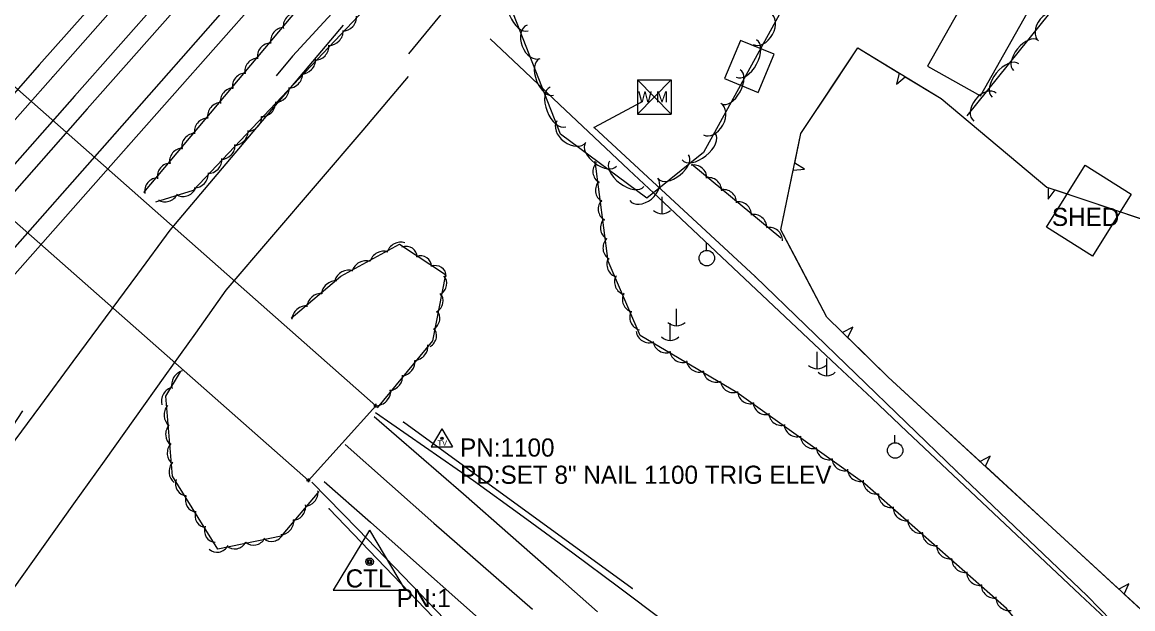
# Model space of a CAD drawing. Extents: x 1441650 to 1491889, y 345904 to 358319.
# Drawn here: x 1442949.9 to 1443255.9, y 356710.4 to 356872.1 of the extents above; entities that cross this region are included whole.
import ezdxf

# ---------------------------------------------------------------- set-up
doc = ezdxf.new("R2010")
doc.units = 0
for name, color, linetype in [('S_BRIDGE', 7, 'Continuous'), ('S_BUILDING', 7, 'Continuous'), ('S_BUILDING_ANNOT', 7, 'Continuous'), ('S_EDGE_PAVEMENT', 7, 'Continuous'), ('S_GRAVEL_ROAD', 7, 'Continuous'), ('S_GUARDRAIL', 7, 'Continuous'), ('S_MSC_PT_SYM', 7, 'Continuous'), ('S_PAVEMENT_CROWN', 7, 'Continuous'), ('S_PRIMARY_CTL', 7, 'Continuous'), ('S_PRIMARY_CTL_ANNOT', 7, 'Continuous'), ('S_RAILROAD', 7, 'Continuous'), ('S_RDW_PT_SYM', 7, 'Continuous'), ('S_SECONDARY_CTL', 7, 'Continuous'), ('S_SECONDARY_CTL_ANNOT', 7, 'Continuous'), ('S_SHOULDER', 7, 'Continuous'), ('S_STR_PT_SYM', 7, 'Continuous'), ('S_STREAM', 7, 'Continuous'), ('S_TREE', 7, 'Continuous'), ('S_UTILITY_POLE', 7, 'Continuous'), ('S_UTL_PT_SYM', 7, 'Continuous'), ('S_WATER_UTILITIES', 7, 'Continuous')]:
    doc.layers.add(name, color=color, linetype=linetype)

msp = doc.modelspace()

# ---------------------------------------------------------------- linework, layer by layer
at = {"layer": 'S_BRIDGE'}
for p, q in [((1443047.33, 356766.4), (1442874.85, 356918.79)), ((1442856.36, 356897.86), (1443028.8, 356745.81)), ((1443028.8, 356745.81), (1443047.33, 356766.4))]:
    msp.add_line(p, q, dxfattribs=at)
at = {"layer": 'S_BUILDING'}
for points in [[(1443227.57, 356909.94), (1443199.41, 356859.94), (1443213.93, 356851.76), (1443231.22, 356882.45), (1443236.84, 356879.29), (1443243.13, 356890.47), (1443237.53, 356893.62), (1443242.11, 356901.75)], [(1443152.76, 356852.67), (1443157.13, 356863.23), (1443147.85, 356867.08), (1443143.48, 356856.52)], [(1443255.53, 356824.71), (1443244.86, 356807.61), (1443232.12, 356815.56), (1443242.79, 356832.66)]]:
    msp.add_lwpolyline(points, close=True, dxfattribs=at)
at = {"layer": 'S_EDGE_PAVEMENT'}
for points in [[(1443046.95, 356763.46), (1443059.25, 356752.76), (1443071.55, 356742.07), (1443084.44, 356730.75), (1443097.33, 356719.43), (1443108.42, 356709.61)], [(1443033.16, 356745.54), (1443045.88, 356734.26), (1443058.61, 356722.97), (1443070.75, 356712.18), (1443082.9, 356701.4)]]:
    msp.add_lwpolyline(points, dxfattribs=at)
at = {"layer": 'S_GRAVEL_ROAD'}
for points in [[(1443151.63, 356970.73), (1443074.25, 356885.2), (1443056.37, 356863.33)], [(1443038.34, 356871.29), (1443026.4, 356857.15), (1443014.47, 356843.02), (1443002.53, 356828.88), (1442990.6, 356814.74), (1442981.69, 356802.67), (1442972.78, 356790.61), (1442963.86, 356778.54), (1442954.95, 356766.48), (1442946.04, 356754.42), (1442937.13, 356742.35), (1442928.22, 356730.29), (1442919.3, 356718.22)], [(1443056.32, 356857.08), (1443043.75, 356842.36), (1443031.19, 356827.64), (1443018.62, 356812.92), (1443006.05, 356798.21), (1442997.66, 356786.43), (1442989.27, 356774.66), (1442980.88, 356762.89), (1442972.5, 356751.12), (1442964.11, 356739.35), (1442955.72, 356727.58), (1442947.33, 356715.81), (1442938.94, 356704.04)]]:
    msp.add_lwpolyline(points, dxfattribs=at)
at = {"layer": 'S_GUARDRAIL'}
for p, q in [((1443118.01, 356716.01), (1443054.97, 356761.85)), ((1443034.47, 356738), (1443088.44, 356681.87))]:
    msp.add_line(p, q, dxfattribs=at)
at = {"layer": 'S_MSC_PT_SYM'}
for points in [[(1442954.65, 356860.32), (1442954.65, 356860.37), (1442954.65, 356860.32), (1442954.6, 356860.32), (1442954.65, 356860.32), (1442954.65, 356860.27), (1442954.65, 356860.32), (1442954.7, 356860.32)], [(1442958.34, 356857.04), (1442958.34, 356857.09), (1442958.34, 356857.04), (1442958.29, 356857.04), (1442958.34, 356857.04), (1442958.34, 356856.99), (1442958.34, 356857.04), (1442958.39, 356857.04)], [(1442964.33, 356851.66), (1442964.33, 356851.71), (1442964.33, 356851.66), (1442964.28, 356851.66), (1442964.33, 356851.66), (1442964.33, 356851.61), (1442964.33, 356851.66), (1442964.38, 356851.66)], [(1442967.86, 356848.17), (1442967.86, 356848.22), (1442967.86, 356848.17), (1442967.81, 356848.17), (1442967.86, 356848.17), (1442967.86, 356848.12), (1442967.86, 356848.17), (1442967.91, 356848.17)], [(1442975.36, 356841.21), (1442975.36, 356841.26), (1442975.36, 356841.21), (1442975.31, 356841.21), (1442975.36, 356841.21), (1442975.36, 356841.16), (1442975.36, 356841.21), (1442975.41, 356841.21)], [(1442979.24, 356838.14), (1442979.24, 356838.19), (1442979.24, 356838.14), (1442979.19, 356838.14), (1442979.24, 356838.14), (1442979.24, 356838.09), (1442979.24, 356838.14), (1442979.29, 356838.14)]]:
    msp.add_lwpolyline(points, dxfattribs=at)
at = {"layer": 'S_PAVEMENT_CROWN'}
msp.add_lwpolyline([(1443038.95, 356755.67), (1443051.16, 356744.86), (1443063.38, 356734.04), (1443076.96, 356722.17), (1443090.55, 356710.29)], dxfattribs=at)
at = {"layer": 'S_PRIMARY_CTL'}
for p, q in [((1443045.64, 356732.08), (1443035.6, 356715.57)), ((1443045.64, 356732.08), (1443055.46, 356715.57)), ((1443035.6, 356715.57), (1443055.46, 356715.57))]:
    msp.add_line(p, q, dxfattribs=at)
for radius in [1.04, 0.609, 0.344]:
    msp.add_circle((1443045.64, 356723.38), radius, dxfattribs=at)
at = {"layer": 'S_RAILROAD'}
for p, q in [((1442986.62, 356896.5), (1442954.65, 356860.32)), ((1442990.28, 356893.3), (1442958.34, 356857.04)), ((1442995.68, 356887.17), (1442964.33, 356851.66)), ((1442999.05, 356883.51), (1442967.86, 356848.17)), ((1443011.76, 356882.6), (1442975.36, 356841.21)), ((1443016.65, 356880.49), (1442979.24, 356838.14)), ((1442954.65, 356860.32), (1442867.45, 356761.69)), ((1442958.34, 356857.04), (1442871.11, 356758.37)), ((1442964.33, 356851.66), (1442876.67, 356752.43)), ((1442967.86, 356848.17), (1442880.75, 356749.56)), ((1442975.36, 356841.21), (1442888.71, 356743.18)), ((1442979.24, 356838.14), (1442889.38, 356736.56))]:
    msp.add_line(p, q, dxfattribs=at)
at = {"layer": 'S_RDW_PT_SYM'}
for points in [[(1443054.97, 356761.85), (1443054.97, 356761.9), (1443054.97, 356761.85), (1443054.92, 356761.85), (1443054.97, 356761.85), (1443054.97, 356761.8), (1443054.97, 356761.85), (1443055.02, 356761.85)], [(1443034.47, 356738), (1443034.47, 356738.05), (1443034.47, 356738), (1443034.42, 356738), (1443034.47, 356738), (1443034.47, 356737.95), (1443034.47, 356738), (1443034.52, 356738)], [(1443118.01, 356716.01), (1443118.01, 356716.06), (1443118.01, 356716.01), (1443117.96, 356716.01), (1443118.01, 356716.01), (1443118.01, 356715.96), (1443118.01, 356716.01), (1443118.06, 356716.01)]]:
    msp.add_lwpolyline(points, dxfattribs=at)
at = {"layer": 'S_SECONDARY_CTL'}
for p, q in [((1443065.58, 356759.98), (1443062.57, 356755.03)), ((1443065.58, 356759.98), (1443068.53, 356755.03)), ((1443062.57, 356755.03), (1443068.53, 356755.03))]:
    msp.add_line(p, q, dxfattribs=at)
for radius in [0.311, 0.183, 0.103]:
    msp.add_circle((1443065.58, 356757.37), radius, dxfattribs=at)
at = {"layer": 'S_SHOULDER'}
for points in [[(1443047.24, 356764.51), (1443060.77, 356755.17), (1443074.29, 356745.83), (1443087.97, 356735.86), (1443101.65, 356725.88), (1443114.21, 356716.46), (1443126.77, 356707.03)], [(1443029.77, 356745.36), (1443042.4, 356732.34), (1443055.03, 356719.33), (1443066.3, 356707.56)]]:
    msp.add_lwpolyline(points, dxfattribs=at)
at = {"layer": 'S_STR_PT_SYM'}
for points in [[(1443047.33, 356766.4), (1443047.33, 356766.9), (1443047.33, 356766.4), (1443046.83, 356766.4), (1443047.33, 356766.4), (1443047.33, 356765.9), (1443047.33, 356766.4), (1443047.83, 356766.4)], [(1443028.8, 356745.81), (1443028.8, 356746.31), (1443028.8, 356745.81), (1443028.3, 356745.81), (1443028.8, 356745.81), (1443028.8, 356745.31), (1443028.8, 356745.81), (1443029.3, 356745.81)]]:
    msp.add_lwpolyline(points, dxfattribs=at)
at = {"layer": 'S_STREAM'}
for points in [[(1443131.3, 356979.88), (1443092.22, 356939.62), (1443051.39, 356892.12), (1443024.43, 356862.76), (1443019.87, 356857.32)], [(1442840.69, 356611.56), (1442873.28, 356652.88), (1442908.54, 356701.31), (1442950.1, 356764.98)]]:
    msp.add_lwpolyline(points, dxfattribs=at)
at = {"layer": 'S_TREE'}
for p, q in [((1443191.57, 356858.08), (1443190.81, 356855.03)), ((1443190.81, 356855.03), (1443193.25, 356857.06)), ((1443165.52, 356831.61), (1443162.79, 356833.21)), ((1443162.39, 356831.29), (1443165.52, 356831.61)), ((1443232.66, 356826.49), (1443232.6, 356823.35)), ((1443232.6, 356823.35), (1443234.52, 356825.87)), ((1443178.8, 356788.02), (1443175.97, 356786.58)), ((1443177.38, 356785.21), (1443178.8, 356788.02)), ((1443216.64, 356752.53), (1443213.86, 356751.02)), ((1443215.31, 356749.69), (1443216.64, 356752.53)), ((1443254.89, 356717.35), (1443252.11, 356715.84)), ((1443253.55, 356714.5), (1443254.89, 356717.35))]:
    msp.add_line(p, q, dxfattribs=at)
for points in [[(1442983.48, 356825.12), (1443029.8, 356880.45), (1443068.95, 356927.1), (1443105.36, 356970.5), (1443136.89, 357005.23)], [(1443123.74, 356966.97), (1443045.8, 356877.25), (1442997.01, 356825.66), (1442986.67, 356822.44)], [(1443171.84, 356898.42), (1443137.65, 356836.14), (1443122, 356823.6), (1443098.21, 356841.22), (1443083.64, 356878.65), (1443109.92, 356917.08), (1443145.8, 356959.84)], [(1443210.26, 356846.31), (1443233.07, 356874.55), (1443252.62, 356884.24)], [(1443078.86, 356867.47), (1443088.43, 356858.46), (1443097.99, 356849.44), (1443107.56, 356840.43), (1443117.12, 356831.42), (1443126.69, 356822.41), (1443136.26, 356813.4), (1443145.82, 356804.39), (1443155.39, 356795.38), (1443164.96, 356786.37), (1443174.52, 356777.36), (1443184.09, 356768.34), (1443193.65, 356759.33), (1443203.22, 356750.32), (1443212.79, 356741.31), (1443222.35, 356732.3), (1443231.92, 356723.29), (1443241.48, 356714.28), (1443251.05, 356705.27)], [(1443078.86, 356867.47), (1443088.43, 356858.46), (1443097.99, 356849.44), (1443107.56, 356840.43), (1443117.12, 356831.42), (1443126.69, 356822.41), (1443136.26, 356813.4), (1443145.82, 356804.39), (1443155.39, 356795.38), (1443164.96, 356786.37), (1443174.52, 356777.36), (1443184.09, 356768.34), (1443193.65, 356759.33), (1443203.22, 356750.32), (1443212.79, 356741.31), (1443222.35, 356732.3), (1443231.92, 356723.29), (1443241.48, 356714.28), (1443251.05, 356705.27)], [(1443505.41, 356683.7), (1443488.39, 356651.81), (1443461.07, 356631.7), (1443424.93, 356601.52), (1443377, 356634.15), (1443309.47, 356701.91), (1443277.71, 356692.29), (1443188.57, 356774.28), (1443171.66, 356790.8), (1443158.99, 356814.85), (1443164.48, 356841.38), (1443180.21, 356864.99), (1443203.13, 356851.04), (1443232.22, 356826.64), (1443267.71, 356814.76), (1443299.03, 356809.84), (1443326.75, 356811.76), (1443339.28, 356826.69)], [(1443173.72, 356855.25), (1443180.21, 356864.99), (1443191.57, 356858.08)], [(1443193.25, 356857.06), (1443203.13, 356851.04), (1443213.42, 356842.42)], [(1443162.79, 356833.21), (1443164.48, 356841.38), (1443173.72, 356855.25)], [(1443213.42, 356842.42), (1443232.22, 356826.64), (1443232.66, 356826.49)], [(1443313.71, 356643.52), (1443306.08, 356628.88), (1443297.66, 356624.12), (1443265.96, 356656.62), (1443221.16, 356710.52), (1443182.13, 356744.91), (1443146.86, 356770.04), (1443120.24, 356785.78), (1443111.42, 356806.27), (1443107.79, 356833.75)], [(1443134.48, 356832.94), (1443158.95, 356812.69)], [(1443162.82, 356807.58), (1443158.99, 356814.85), (1443162.39, 356831.29)], [(1443234.52, 356825.87), (1443258.23, 356817.93)], [(1443024.03, 356790.49), (1443037.75, 356802.12), (1443053.93, 356810.94), (1443066.58, 356802.55), (1443062.95, 356784.27), (1443047.75, 356765.83)], [(1443175.97, 356786.58), (1443171.66, 356790.8), (1443162.82, 356807.58)], [(1443195.46, 356767.94), (1443188.57, 356774.28), (1443177.38, 356785.21)], [(1443031.65, 356742.72), (1443021.25, 356730.46), (1443003.84, 356726.88), (1442991.3, 356747.02), (1442989.51, 356769.04), (1442993.51, 356775.69)], [(1443213.86, 356751.02), (1443195.46, 356767.94)], [(1443233.71, 356732.76), (1443215.31, 356749.69)], [(1443252.11, 356715.84), (1443233.71, 356732.76)], [(1443271.95, 356697.58), (1443253.55, 356714.5)]]:
    msp.add_lwpolyline(points, dxfattribs=at)
for centre in [(1443134.96, 356829.09), (1443139.02, 356825.63), (1443143.14, 356822.32), (1443147.25, 356818.97), (1443151.44, 356815.49), (1443155.77, 356811.87)]:
    msp.add_arc(centre, 3.64, 359.5936, 101.1906, dxfattribs=at)
for centre, major_axis, ratio, start_param, end_param in [((1443087.25, 356875.21), (2.13, -5.47), 0.550077, 3.141593, 6.283185), ((1443233.08, 356870.78), (-3.11, -3.86), 0.684333, 3.141593, 6.283185), ((1443025.43, 356871.09), (-2.45, -2.7), 0.970025, 3.866419, 5.63962), ((1443038.65, 356873.11), (2.49, 2.66), 0.892116, 3.819515, 5.592715), ((1443153.69, 356870.3), (2.38, 4.34), 0.685297, 3.141593, 6.283185), ((1443021.95, 356867.05), (-2.45, -2.7), 0.970025, 3.866419, 5.63962), ((1443034.91, 356869.15), (2.49, 2.66), 0.892116, 3.819515, 5.592715), ((1443090.86, 356866.68), (1.8, -4.62), 0.685307, 3.141593, 6.283185), ((1443018.3, 356862.74), (-2.45, -2.7), 0.970025, 3.866419, 5.63962), ((1443031.01, 356865.07), (2.49, 2.66), 0.892116, 3.819515, 5.592715), ((1443149.46, 356862.06), (2.82, 5.14), 0.550069, 3.141593, 6.283185), ((1443226.41, 356862.93), (-3.36, -4.16), 0.539928, 3.141593, 6.283185), ((1443014.81, 356858.57), (-2.45, -2.7), 0.970025, 3.866419, 5.63962), ((1443027.3, 356861.24), (2.49, 2.66), 0.892116, 3.819515, 5.592715), ((1443094.35, 356856.98), (1.94, -4.98), 0.540696, 3.141593, 6.283185), ((1443220.84, 356856.03), (-3.69, -4.57), 0.549295, 3.141593, 6.283185), ((1443011.43, 356854.48), (-2.45, -2.7), 0.970025, 3.866419, 5.63962), ((1443023.72, 356857.36), (2.49, 2.66), 0.892116, 3.819515, 5.592715), ((1443145.19, 356854.28), (2.57, 4.69), 0.540688, 3.141593, 6.283185), ((1443008.09, 356850.38), (-2.45, -2.7), 0.970025, 3.866419, 5.63962), ((1443020.1, 356853.48), (2.49, 2.66), 0.892116, 3.819515, 5.592715), ((1443097.57, 356848.72), (2.13, -5.47), 0.550077, 3.141593, 6.283185), ((1443215.22, 356848.67), (-3.11, -3.86), 0.684333, 3.141593, 6.283185), ((1443004.61, 356846.34), (-2.45, -2.7), 0.970025, 3.866419, 5.63962), ((1443016.35, 356849.53), (2.49, 2.66), 0.892116, 3.819515, 5.592715), ((1443140.01, 356845.38), (2.38, 4.34), 0.685297, 3.141593, 6.283185), ((1443000.96, 356842.03), (-2.45, -2.7), 0.970025, 3.866419, 5.63962), ((1443012.45, 356845.45), (2.49, 2.66), 0.892116, 3.819515, 5.592715), ((1443101.26, 356841.92), (3.98, -2.95), 0.685376, 3.141591, 6.283183), ((1442997.47, 356837.86), (-2.45, -2.7), 0.970025, 3.866419, 5.63962), ((1443008.74, 356841.62), (2.49, 2.66), 0.892116, 3.819515, 5.592715), ((1443136.31, 356837.78), (4.58, 3.67), 0.550069, 3.141593, 6.283185), ((1443005.16, 356837.73), (2.49, 2.66), 0.892116, 3.819515, 5.592715), ((1443109.39, 356835.58), (4.3, -3.18), 0.540751, 3.141592, 6.283184), ((1442994.09, 356833.77), (-2.45, -2.7), 0.970025, 3.866419, 5.63962), ((1443129.38, 356832.23), (4.17, 3.34), 0.540689, 3.141593, 6.283185), ((1442990.75, 356829.68), (-2.45, -2.7), 0.970025, 3.866419, 5.63962), ((1443001.54, 356833.86), (2.49, 2.66), 0.892116, 3.819515, 5.592715), ((1443110.81, 356830.93), (3.63, -0.32), 0.98482, 2.470246, 4.243447), ((1443116.51, 356830.31), (4.72, -3.49), 0.550133, 3.141592, 6.283184), ((1442987.27, 356825.63), (-2.45, -2.7), 0.970025, 3.866419, 5.63962), ((1442997.8, 356829.91), (2.49, 2.66), 0.892116, 3.819515, 5.592715), ((1443121.18, 356826), (3.87, 3.1), 0.685297, 3.141593, 6.283185), ((1442994.66, 356827.49), (2.46, 2.68), 0.892097, 3.248047, 5.021248), ((1443111.53, 356825.75), (3.63, -0.32), 0.98482, 2.470246, 4.243447), ((1442989.71, 356826.02), (2.46, 2.68), 0.892097, 3.248047, 5.021248), ((1443112.28, 356820.6), (3.63, -0.32), 0.98482, 2.470246, 4.243447), ((1443112.9, 356815.38), (3.63, -0.32), 0.98482, 2.470246, 4.243447), ((1443053.72, 356808.16), (-2.83, -2.3), 0.849866, 3.611023, 5.384224), ((1443113.59, 356809.86), (3.63, -0.32), 0.98482, 2.470246, 4.243447), ((1443049.04, 356805.68), (-2.83, -2.3), 0.849866, 3.611023, 5.384224), ((1443055.25, 356806.91), (-2.9, -2.21), 0.884338, 2.551956, 4.325157), ((1443059.22, 356804.32), (-2.9, -2.21), 0.884338, 2.551956, 4.325157), ((1443044.1, 356803.02), (-2.83, -2.3), 0.849866, 3.611023, 5.384224), ((1443063.28, 356801.62), (-2.9, -2.21), 0.884338, 2.551956, 4.325157), ((1443114.66, 356805.37), (3.62, -0.45), 0.99684, 2.784185, 4.557386), ((1443039.35, 356800.43), (-2.83, -2.3), 0.849866, 3.611023, 5.384224), ((1443063.51, 356799.58), (2.88, 2.23), 0.839526, 4.628666, 6.401866), ((1443116.78, 356800.53), (3.62, -0.45), 0.99684, 2.784185, 4.557386), ((1443035.75, 356797.45), (-2.78, -2.36), 0.849261, 3.825789, 5.598989), ((1443031.76, 356793.99), (-2.78, -2.36), 0.849261, 3.825789, 5.598989), ((1443062.49, 356794.77), (2.88, 2.23), 0.839526, 4.628666, 6.401866), ((1443118.94, 356795.72), (3.62, -0.45), 0.99684, 2.784185, 4.557386), ((1443027.65, 356790.59), (-2.78, -2.36), 0.849261, 3.825789, 5.598989), ((1443061.61, 356790), (2.88, 2.23), 0.839526, 4.628666, 6.401866), ((1443120.98, 356790.8), (3.62, -0.45), 0.99684, 2.784185, 4.557386), ((1443060.69, 356785.21), (2.88, 2.23), 0.839526, 4.628666, 6.401866), ((1443122.7, 356787.38), (1.33, -3.39), 0.998984, 4.490045, 6.263245), ((1443058.27, 356782.14), (2.93, 2.17), 0.845103, 4.111887, 5.885088), ((1443127.38, 356784.61), (1.33, -3.39), 0.998984, 4.490045, 6.263245), ((1443131.97, 356781.94), (1.33, -3.39), 0.998984, 4.490045, 6.263245), ((1443054.7, 356777.84), (2.93, 2.17), 0.845103, 4.111887, 5.885088), ((1443136.55, 356779.31), (1.33, -3.39), 0.998984, 4.490045, 6.263245), ((1442994.44, 356772.51), (-1.93, -3.09), 0.891178, 3.845584, 5.618785), ((1443051.3, 356773.81), (2.93, 2.17), 0.845103, 4.111887, 5.885088), ((1443141.1, 356776.53), (1.33, -3.39), 0.998984, 4.490045, 6.263245), ((1442991.63, 356767.97), (-1.93, -3.09), 0.891178, 3.845584, 5.618785), ((1443048.03, 356769.74), (2.93, 2.17), 0.845103, 4.111887, 5.885088), ((1443145.94, 356773.63), (1.33, -3.39), 0.998984, 4.490045, 6.263245), ((1443150.64, 356770.57), (-1.41, -3.36), 0.98519, 5.179577, 6.952778), ((1442992.32, 356764.07), (-1.09, -3.48), 0.895938, 4.251056, 6.024257), ((1443154.91, 356767.56), (-1.41, -3.36), 0.98519, 5.179577, 6.952778), ((1443159.2, 356764.6), (-1.41, -3.36), 0.98519, 5.179577, 6.952778), ((1442992.75, 356758.73), (-1.09, -3.48), 0.895938, 4.251056, 6.024257), ((1443163.44, 356761.49), (-1.41, -3.36), 0.98519, 5.179577, 6.952778), ((1442993.2, 356753.54), (-1.09, -3.48), 0.895938, 4.251056, 6.024257), ((1443167.95, 356758.23), (-1.41, -3.36), 0.98519, 5.179577, 6.952778), ((1443172.32, 356755.12), (-1.41, -3.36), 0.98519, 5.179577, 6.952778), ((1442993.69, 356748.38), (-1.09, -3.48), 0.895938, 4.251056, 6.024257), ((1443176.6, 356752.11), (-1.41, -3.36), 0.98519, 5.179577, 6.952778), ((1443180.88, 356749.15), (-1.41, -3.36), 0.98519, 5.179577, 6.952778), ((1442995.45, 356745.2), (-1.36, -3.38), 0.886467, 4.821386, 6.594586), ((1443185.26, 356745.7), (2.35, -2.78), 0.999243, 3.971621, 5.744821), ((1442998.18, 356740.76), (-1.36, -3.38), 0.886467, 4.821386, 6.594586), ((1443028.22, 356742.37), (0.94, 3.52), 0.876734, 3.329966, 5.103166), ((1443189.47, 356741.94), (2.35, -2.78), 0.999243, 3.971621, 5.744821), ((1443000.82, 356736.5), (-1.36, -3.38), 0.886467, 4.821386, 6.594586), ((1443024.81, 356738.46), (0.94, 3.52), 0.876734, 3.329966, 5.103166), ((1443193.55, 356738.34), (2.35, -2.78), 0.999243, 3.971621, 5.744821), ((1443021.53, 356734.49), (0.94, 3.52), 0.876734, 3.329966, 5.103166), ((1443197.56, 356734.86), (2.35, -2.78), 0.999243, 3.971621, 5.744821), ((1443003.43, 356732.37), (-1.36, -3.38), 0.886467, 4.821386, 6.594586), ((1443201.57, 356731.43), (2.35, -2.78), 0.999243, 3.971621, 5.744821), ((1443008.72, 356730.52), (1.55, 3.3), 0.907973, 2.851056, 4.624256), ((1443013.91, 356731.55), (1.55, 3.3), 0.907973, 2.851056, 4.624256), ((1443018.91, 356732.58), (1.55, 3.3), 0.907973, 2.851056, 4.624256), ((1443205.52, 356727.84), (2.35, -2.78), 0.999243, 3.971621, 5.744821), ((1443003.81, 356729.58), (1.55, 3.3), 0.907973, 2.851056, 4.624256), ((1443209.74, 356724.09), (2.35, -2.78), 0.999243, 3.971621, 5.744821), ((1443213.82, 356720.49), (2.35, -2.78), 0.999243, 3.971621, 5.744821), ((1443217.82, 356717.01), (2.35, -2.78), 0.999243, 3.971621, 5.744821), ((1443221.83, 356713.57), (2.35, -2.78), 0.999243, 3.971621, 5.744821)]:
    msp.add_ellipse(centre, major_axis=major_axis, ratio=ratio, start_param=start_param, end_param=end_param, dxfattribs=at)
at = {"layer": 'S_UTILITY_POLE'}
for p, q in [((1443126.16, 356823.99), (1443126.16, 356819.26)), ((1443138.44, 356809.21), (1443138.44, 356811.32)), ((1443130.15, 356793.12), (1443130.15, 356788.4)), ((1443128.41, 356789.12), (1443128.41, 356784.4)), ((1443168.92, 356781.27), (1443168.92, 356776.54)), ((1443171.54, 356779.39), (1443171.54, 356774.66)), ((1443190.35, 356756.21), (1443190.35, 356758.32))]:
    msp.add_line(p, q, dxfattribs=at)
for centre in [(1443138.56, 356807.07), (1443190.47, 356754.07)]:
    msp.add_circle(centre, 2.13, dxfattribs=at)
for centre in [(1443126.22, 356822.69), (1443130.21, 356791.82), (1443128.47, 356787.82), (1443168.98, 356779.97), (1443171.6, 356778.08)]:
    msp.add_arc(centre, 3.41, 226.3972, 313.6028, dxfattribs=at)
at = {"layer": 'S_UTL_PT_SYM'}
for points in [[(1443120.38, 356849.93), (1443120.38, 356849.98), (1443120.38, 356849.93), (1443120.33, 356849.93), (1443120.38, 356849.93), (1443120.38, 356849.88), (1443120.38, 356849.93), (1443120.43, 356849.93)], [(1443107.52, 356843.09), (1443107.52, 356843.14), (1443107.52, 356843.09), (1443107.47, 356843.09), (1443107.52, 356843.09), (1443107.52, 356843.04), (1443107.52, 356843.09), (1443107.57, 356843.09)], [(1443151.88, 356802.02), (1443151.88, 356802.07), (1443151.88, 356802.02), (1443151.83, 356802.02), (1443151.88, 356802.02), (1443151.88, 356801.97), (1443151.88, 356802.02), (1443151.93, 356802.02)], [(1443207.39, 356748.36), (1443207.39, 356748.41), (1443207.39, 356748.36), (1443207.34, 356748.36), (1443207.39, 356748.36), (1443207.39, 356748.31), (1443207.39, 356748.36), (1443207.44, 356748.36)], [(1443243.37, 356714.04), (1443243.37, 356714.09), (1443243.37, 356714.04), (1443243.32, 356714.04), (1443243.37, 356714.04), (1443243.37, 356713.99), (1443243.37, 356714.04), (1443243.42, 356714.04)]]:
    msp.add_lwpolyline(points, dxfattribs=at)
at = {"layer": 'S_WATER_UTILITIES'}
for p, q in [((1443119.43, 356856.22), (1443128.77, 356856.22)), ((1443119.43, 356856.22), (1443119.43, 356846.73)), ((1443119.43, 356856.22), (1443128.77, 356846.73)), ((1443128.77, 356856.22), (1443119.43, 356846.73)), ((1443128.77, 356856.22), (1443128.77, 356846.73)), ((1443120.38, 356849.93), (1443107.52, 356843.09)), ((1443119.43, 356846.73), (1443128.77, 356846.73)), ((1443107.52, 356843.09), (1443151.88, 356802.02)), ((1443151.88, 356802.02), (1443207.39, 356748.36)), ((1443207.39, 356748.36), (1443243.37, 356714.04)), ((1443243.37, 356714.04), (1443339.17, 356615.94))]:
    msp.add_line(p, q, dxfattribs=at)

# ---------------------------------------------------------------- texts
at = {"layer": 'S_BUILDING_ANNOT'}
msp.add_text('SHED', height=5, dxfattribs=at).set_placement((1443233.65, 356815.94))
at = {"layer": 'S_PRIMARY_CTL'}
msp.add_text('CTL', height=5, rotation=360, dxfattribs=at).set_placement((1443039.05, 356716.3))
at = {"layer": 'S_PRIMARY_CTL_ANNOT'}
msp.add_text('PN:1', height=5, dxfattribs=at).set_placement((1443053.14, 356710.88))
at = {"layer": 'S_SECONDARY_CTL'}
msp.add_text('TV', height=1.5, rotation=360, dxfattribs=at).set_placement((1443064.37, 356755.36))
at = {"layer": 'S_SECONDARY_CTL_ANNOT'}
for s, p in [('PN:1100', (1443070.58, 356752.37)), ('PD:SET 8" NAIL 1100 TRIG ELEV', (1443070.58, 356744.87))]:
    msp.add_text(s, height=5, dxfattribs=at).set_placement(p)
at = {"layer": 'S_WATER_UTILITIES'}
msp.add_text('W M', height=3, rotation=360, dxfattribs=at).set_placement((1443119.64, 356849.99))

doc.saveas('drawing.dxf')
